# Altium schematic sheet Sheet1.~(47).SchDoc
size A4; SheetNumber: 1; SheetTotal: 1
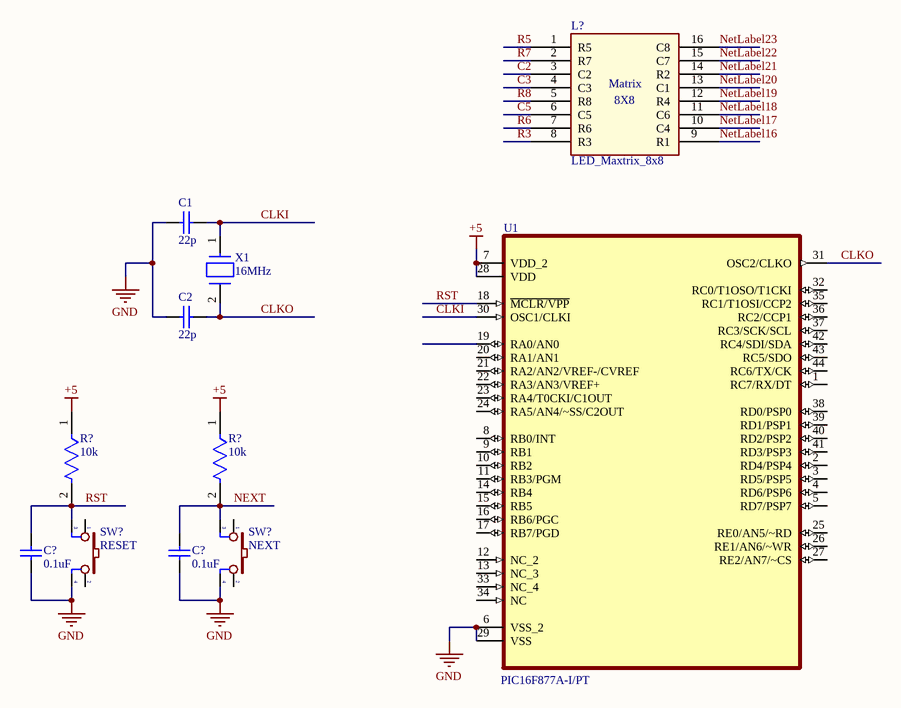
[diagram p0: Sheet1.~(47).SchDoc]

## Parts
(Parts that share a designator on the sheet are numbered #1, #2 ... from top to bottom, then left to right.)
C1  22p  [CAPC2013X94X50LL25T25]
C2  22p  [CAPC2013X94X50LL25T25]
C?#1  0.1uF  [CAPC2013X94X50LL25T25]
C?#2  0.1uF  [CAPC2013X94X50LL25T25]
L?  LED_Maxtrix_8x8  [LED_Matrix_8x8]
R?#1  10k  [FP-CR0805-MFG]
R?#2  10k  [FP-CR0805-MFG]
SW?#1  RESET  [SW4]
SW?#2  NEXT  [SW4]
U1  PIC16F877A-I/PT  [TQFP-44]
X1  16MHz  [FP-ABM7-MFG]

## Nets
+5: R?#1.1 R?#2.1 U1.7(VDD_2) U1.28(VDD)
GND: C1.1 C2.1 C?#1.1 C?#2.1 SW?#1.4 SW?#2.4 U1.6(VSS_2) U1.29(VSS)
C2: L?.3(C2)
C3: L?.4(C3)
C5: L?.6(C5)
CLKI: C1.2 U1.30(OSC1/CLKI) X1.1
CLKO: C2.2 U1.31(OSC2/CLKO) X1.2
NetLabel16: L?.9(R1)
NetLabel17: L?.10(C4)
NetLabel18: L?.11(C6)
NetLabel19: L?.12(R4)
NetLabel20: L?.13(C1)
NetLabel21: L?.14(R2)
NetLabel22: L?.15(C7)
NetLabel23: L?.16(C8)
NEXT: C?#2.2 R?#2.2 SW?#2.3
R3: L?.8(R3)
R5: L?.1(R5)
R6: L?.7(R6)
R7: L?.2(R7)
R8: L?.5(R8)
RST: C?#1.2 R?#1.2 SW?#1.3 U1.18(~{MCLR/VPP})

Not connected (* = marked no-connect by the designer): SW?#1 1 2; SW?#2 1 2; U1 1(RC7/RX/DT) 2(RD4/PSP4) 3(RD5/PSP5) 4(RD6/PSP6) 5(RD7/PSP7) 8(RB0/INT) 9(RB1) 10(RB2) 11(RB3/PGM) 12(NC_2) 13(NC_3) 14(RB4) 15(RB5) 16(RB6/PGC) 17(RB7/PGD) 19(RA0/AN0) 20(RA1/AN1) 21(RA2/AN2/VREF-/CVREF) 22(RA3/AN3/VREF+) 23(RA4/T0CKI/C1OUT) 24(RA5/AN4/~SS/C2OUT) 25(RE0/AN5/~RD) 26(RE1/AN6/~WR) 27(RE2/AN7/~CS) 32(RC0/T1OSO/T1CKI) 33(NC_4) 34(NC) 35(RC1/T1OSI/CCP2) 36(RC2/CCP1) 37(RC3/SCK/SCL) 38(RD0/PSP0) 39(RD1/PSP1) 40(RD2/PSP2) 41(RD3/PSP3) 42(RC4/SDI/SDA) 43(RC5/SDO) 44(RC6/TX/CK)

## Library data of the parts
C1 C2 C?#1 C?#2 = LD051C104KAB2A: Cap Ceramic 0.1uF 100V X7R 10% SMD 0805 125°C Embossed T/R; Manufacturer: Kyocera AVX; Value: 100nF
R?#1 R?#2 = CR0805-JW-331ELF: Res Thick Film 0805 330 Ohm 5% 1/8W ±200ppm/°C Molded SMD SMD Paper Tape on Plastic Reel; Manufacturer: Bourns; Value: 330R; Power Rating: 125mW; Voltage Rating: 150V
SW?#1 SW?#2 = SW4-1: Switch button 4 pin; Value: SW chip 4 pin
U1 = PIC16F877A-I/PT: PIC16F877A Microcontroller IC 8-Bit 20MHz 14KB _8K x 14_ FLASH 44-TQFP _10x10_; MF: Microchip
X1 = ABM7-16.000MHZ-4-T: Crystal 16MHz ±30ppm (Tol) ±50ppm (Stability) 18pF FUND 50Ohm 2-Pin Mini-CSMD T/R; Manufacturer: Abracon; ESR (Equivalent Series Resistance): 50R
